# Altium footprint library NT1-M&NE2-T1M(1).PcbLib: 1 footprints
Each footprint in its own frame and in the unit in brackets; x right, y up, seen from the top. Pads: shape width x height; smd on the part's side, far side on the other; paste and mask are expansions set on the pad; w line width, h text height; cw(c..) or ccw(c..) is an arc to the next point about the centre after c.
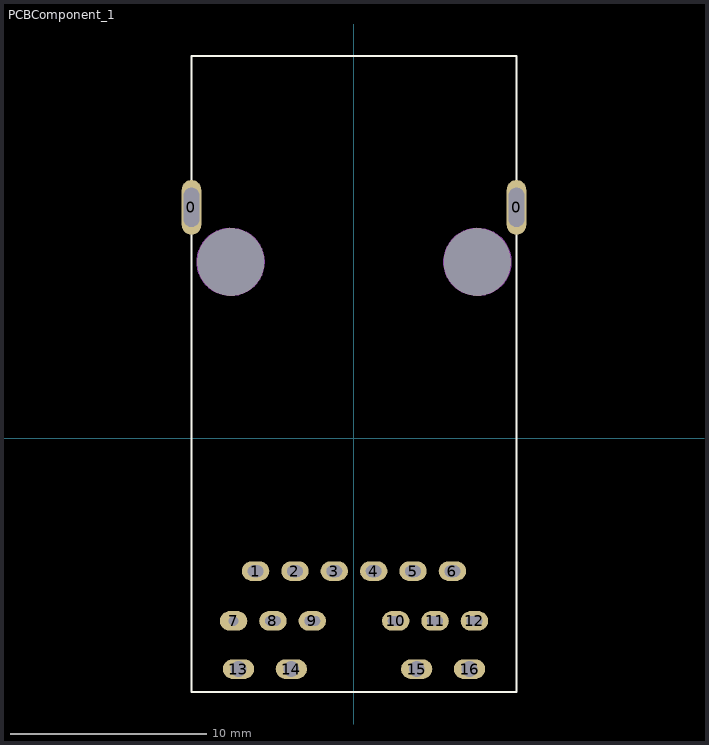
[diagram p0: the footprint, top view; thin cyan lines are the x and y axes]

## PCBComponent_1 [mm]
pads (18):
  oval 1x2.8 hole 0.8 slot 2 at 90 deg mask+0.01: 0(-8.3,11.79) 0(8.3,11.79)
  oval 1.4x1 hole 0.6 slot 0.8 at 0 deg: 1(-5.025,-6.79) 2(-3.015,-6.79) 3(-1.005,-6.79) 4(1.005,-6.79) 5(3.015,-6.79) 6(5.025,-6.79)
  oval 1.4x1 hole 0.5 mask+0.01: 7(-6.15,-9.33)
  oval 1.4x1 hole 0.5 slot 0.8 at 0 deg mask+0.01: 8(-4.14,-9.33) 9(-2.13,-9.33) 10(2.13,-9.33) 11(4.14,-9.33) 12(6.15,-9.33)
  oval 1.6x1 hole 0.8 mask+0.01: 13(-5.9,-11.79) 14(-3.2,-11.79) 15(3.2,-11.79) 16(5.9,-11.79)
via 6.3,9 diameter 3.4 hole 3.4
via -6.3,9 diameter 3.4 hole 3.4
Top Overlay:
  lines w0.1: -8.3,-12.97 -8.3,19.53 8.3,19.53 8.3,-12.97 -8.3,-12.97
Keep-Out Layer:
  circle w0.1: c-6.3,9 r1.641
Mechanical 1:
  circle w0.1: c6.3,9.005 r1.7
  circle w0.1: c-6.3,9.005 r1.7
